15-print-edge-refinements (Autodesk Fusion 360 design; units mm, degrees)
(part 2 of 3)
sketch "B Facet 180 Triangle 3" plane through (0, -75, 0) normal (0, -1, 0) x axis (-1, 0, 0)
  line L1 (60.9665, 27.066) -> (-2.067, -27.066)
  line L2 (124, -27.066) -> (60.9665, 27.066)
  line L3 (-2.067, -27.066) -> (124, -27.066)
  line L4 (60.9665, 21.7934) -> (8.7304, -23.066)
  line L5 (113.2026, -23.066) -> (60.9665, 21.7934)
  line L6 (8.7304, -23.066) -> (113.2026, -23.066)
  point P1 (0, 0)
  point P2 (-2.067, -27.066)
  point P3 (60.9665, 27.066)
  point P4 (124, -27.066)
  dimension "d477" distance P1 P2 = 2.067 (= "Linear Dimension-2")
  dimension "d478" distance P1 P2 = 27.066 (= "Linear Dimension-3")
  dimension "d479" distance P1 P3 = 60.9665 (= "Linear Dimension-4")
  dimension "d480" distance P1 P3 = 27.066 (= "Linear Dimension-5")
  dimension "d481" distance P1 P4 = 124 (= "Linear Dimension-6")
  dimension "d482" distance P1 P4 = 27.066 (= "Linear Dimension-7")
  dimension "d483" = 4 (= "memberWidth / 2")
extrude "Extrude14" cut sketch "B Facet 180 Triangle 3" profile of L5 L6 L4 against normal blind 4.7 (magnitude of "-( wall + 0.2 mm )")
sketch "B Facet 180 Triangle 4" plane through (0, -75, 0) normal (0, -1, 0) x axis (-1, 0, 0)
  line L1 (124, -27.066) -> (60.9665, 27.066)
  line L2 (124, 27.066) -> (124, -27.066)
  line L3 (60.9665, 27.066) -> (124, 27.066)
  line L4 (120, -18.3583) -> (71.7639, 23.066)
  line L5 (120, 23.066) -> (120, -18.3583)
  line L6 (71.7639, 23.066) -> (120, 23.066)
  point P1 (0, 0)
  point P2 (60.9665, 27.066)
  point P3 (124, -27.066)
  point P4 (124, 27.066)
  dimension "d486" distance P1 P2 = 60.9665 (= "Linear Dimension-2")
  dimension "d487" distance P1 P2 = 27.066 (= "Linear Dimension-3")
  dimension "d488" distance P1 P3 = 124 (= "Linear Dimension-4")
  dimension "d489" distance P1 P3 = 27.066 (= "Linear Dimension-5")
  dimension "d490" distance P1 P4 = 124 (= "Linear Dimension-6")
  dimension "d491" distance P1 P4 = 27.066 (= "Linear Dimension-7")
  dimension "d492" = -4 (= "-memberWidth / 2")
extrude "Extrude15" cut sketch "B Facet 180 Triangle 4" profile of L5 L6 L4 against normal blind 4.7 (magnitude of "-( wall + 0.2 mm )")
fillet "Fillet5" radius 1.5 (= "apertureRadius")
work_plane "WorkPlane11" RotateAngle 135 ExtraOffset 0
work_plane "WorkPlane12" AlongDistance 75 (= "bodyWidth / 2") ExtraOffset 0
sketch "B Facet 225 Triangle 1" plane through (0, -53.033, -53.033) normal (0, -0.7071, -0.7071) x axis (1, 0, 0)
  line L1 (23.9949, -27.066) -> (62.2721, 27.066)
  line L2 (0.1814, 27.066) -> (23.9949, -27.066)
  line L3 (62.2721, 27.066) -> (0.1814, 27.066)
  line L4 (24.81, -18.9852) -> (54.5447, 23.066)
  line L5 (6.311, 23.066) -> (24.81, -18.9852)
  line L6 (54.5447, 23.066) -> (6.311, 23.066)
  point P1 (0, 0)
  point P2 (62.2721, 27.066)
  point P3 (23.9949, -27.066)
  point P4 (0.1814, 27.066)
  dimension "d501" distance P1 P2 = 62.2721 (= "Linear Dimension-2")
  dimension "d502" distance P1 P2 = 27.066 (= "Linear Dimension-3")
  dimension "d503" distance P1 P3 = 23.9949 (= "Linear Dimension-4")
  dimension "d504" distance P1 P3 = 27.066 (= "Linear Dimension-5")
  dimension "d505" distance P1 P4 = 0.1814 (= "Linear Dimension-6")
  dimension "d506" distance P1 P4 = 27.066 (= "Linear Dimension-7")
  dimension "d507" = 4 (= "memberWidth / 2")
extrude "Extrude16" cut sketch "B Facet 225 Triangle 1" profile of L5 L6 L4 against normal blind 4.7 (magnitude of "-( wall + 0.2 mm )")
sketch "B Facet 225 Triangle 2" plane through (0, -53.033, -53.033) normal (0, -0.7071, -0.7071) x axis (1, 0, 0)
  line L1 (0.1814, 27.066) -> (23.9949, -27.066)
  line L2 (-74.6684, -27.066) -> (0.1814, 27.066)
  line L3 (23.9949, -27.066) -> (-74.6684, -27.066)
  line L4 (-1.4863, 20.9235) -> (17.8653, -23.066)
  line L5 (-62.3117, -23.066) -> (-1.4863, 20.9235)
  line L6 (17.8653, -23.066) -> (-62.3117, -23.066)
  point P1 (0, 0)
  point P2 (23.9949, -27.066)
  point P3 (0.1814, 27.066)
  point P4 (-74.6684, -27.066)
  dimension "d510" distance P1 P2 = 23.9949 (= "Linear Dimension-2")
  dimension "d511" distance P1 P2 = 27.066 (= "Linear Dimension-3")
  dimension "d512" distance P1 P3 = 0.1814 (= "Linear Dimension-4")
  dimension "d513" distance P1 P3 = 27.066 (= "Linear Dimension-5")
  dimension "d514" distance P1 P4 = 74.6684 (= "Linear Dimension-6")
  dimension "d515" distance P1 P4 = 27.066 (= "Linear Dimension-7")
  dimension "d516" = -4 (= "-memberWidth / 2")
extrude "Extrude17" cut sketch "B Facet 225 Triangle 2" profile of L5 L6 L4 against normal blind 4.7 (magnitude of "-( wall + 0.2 mm )")
sketch "B Facet 225 Triangle 3" plane through (0, -53.033, -53.033) normal (0, -0.7071, -0.7071) x axis (1, 0, 0)
  line L1 (-74.6684, -27.066) -> (0.1814, 27.066)
  line L2 (-124, 27.066) -> (-74.6684, -27.066)
  line L3 (0.1814, 27.066) -> (-124, 27.066)
  line L4 (-74.1179, -21.7315) -> (-12.1753, 23.066)
  line L5 (-114.9429, 23.066) -> (-74.1179, -21.7315)
  line L6 (-12.1753, 23.066) -> (-114.9429, 23.066)
  point P1 (0, 0)
  point P2 (0.1814, 27.066)
  point P3 (-74.6684, -27.066)
  point P4 (-124, 27.066)
  dimension "d519" distance P1 P2 = 0.1814 (= "Linear Dimension-2")
  dimension "d520" distance P1 P2 = 27.066 (= "Linear Dimension-3")
  dimension "d521" distance P1 P3 = 74.6684 (= "Linear Dimension-4")
  dimension "d522" distance P1 P3 = 27.066 (= "Linear Dimension-5")
  dimension "d523" distance P1 P4 = 124 (= "Linear Dimension-6")
  dimension "d524" distance P1 P4 = 27.066 (= "Linear Dimension-7")
  dimension "d525" = 4 (= "memberWidth / 2")
extrude "Extrude18" cut sketch "B Facet 225 Triangle 3" profile of L5 L6 L4 against normal blind 4.7 (magnitude of "-( wall + 0.2 mm )")
sketch "B Facet 225 Triangle 4" plane through (0, -53.033, -53.033) normal (0, -0.7071, -0.7071) x axis (1, 0, 0)
  line L1 (-124, 27.066) -> (-74.6684, -27.066)
  line L2 (-124, -27.066) -> (-124, 27.066)
  line L3 (-74.6684, -27.066) -> (-124, -27.066)
  line L4 (-120, 16.7383) -> (-83.7255, -23.066)
  line L5 (-120, -23.066) -> (-120, 16.7383)
  line L6 (-83.7255, -23.066) -> (-120, -23.066)
  point P1 (0, 0)
  point P2 (-74.6684, -27.066)
  point P3 (-124, 27.066)
  point P4 (-124, -27.066)
  dimension "d528" distance P1 P2 = 74.6684 (= "Linear Dimension-2")
  dimension "d529" distance P1 P2 = 27.066 (= "Linear Dimension-3")
  dimension "d530" distance P1 P3 = 124 (= "Linear Dimension-4")
  dimension "d531" distance P1 P3 = 27.066 (= "Linear Dimension-5")
  dimension "d532" distance P1 P4 = 124 (= "Linear Dimension-6")
  dimension "d533" distance P1 P4 = 27.066 (= "Linear Dimension-7")
  dimension "d534" = -4 (= "-memberWidth / 2")
extrude "Extrude19" cut sketch "B Facet 225 Triangle 4" profile of L5 L6 L4 against normal blind 4.7 (magnitude of "-( wall + 0.2 mm )")
fillet "Fillet6" radius 1.5 (= "apertureRadius")
work_plane "WorkPlane13" RotateAngle 180 ExtraOffset 0
work_plane "WorkPlane14" AlongDistance 75 (= "bodyWidth / 2") ExtraOffset 0
sketch "B Facet 270 Triangle 1" plane through (0, 0, -75) normal (0, 0, -1) x axis (-1, 0, 0)
  line L1 (36.9655, 27.066) -> (-17.1665, -27.066)
  line L2 (53.4167, -27.066) -> (36.9655, 27.066)
  line L3 (-17.1665, -27.066) -> (53.4167, -27.066)
  line L4 (35.0777, 19.5214) -> (-7.5097, -23.066)
  line L5 (48.0205, -23.066) -> (35.0777, 19.5214)
  line L6 (-7.5097, -23.066) -> (48.0205, -23.066)
  point P1 (0, 0)
  point P2 (-17.1665, -27.066)
  point P3 (36.9655, 27.066)
  point P4 (53.4167, -27.066)
  dimension "d543" distance P1 P2 = 17.1665 (= "Linear Dimension-2")
  dimension "d544" distance P1 P2 = 27.066 (= "Linear Dimension-3")
  dimension "d545" distance P1 P3 = 36.9655 (= "Linear Dimension-4")
  dimension "d546" distance P1 P3 = 27.066 (= "Linear Dimension-5")
  dimension "d547" distance P1 P4 = 53.4167 (= "Linear Dimension-6")
  dimension "d548" distance P1 P4 = 27.066 (= "Linear Dimension-7")
  dimension "d549" = 4 (= "memberWidth / 2")
extrude "Extrude20" cut sketch "B Facet 270 Triangle 1" profile of L5 L6 L4 against normal blind 4.7 (magnitude of "-( wall + 0.2 mm )")
sketch "B Facet 270 Triangle 2" plane through (0, 0, -75) normal (0, 0, -1) x axis (-1, 0, 0)
  line L1 (53.4167, -27.066) -> (36.9655, 27.066)
  line L2 (124, 27.066) -> (53.4167, -27.066)
  line L3 (36.9655, 27.066) -> (124, 27.066)
  line L4 (55.5648, -20.3777) -> (42.3618, 23.066)
  line L5 (112.2115, 23.066) -> (55.5648, -20.3777)
  line L6 (42.3618, 23.066) -> (112.2115, 23.066)
  point P1 (0, 0)
  point P2 (36.9655, 27.066)
  point P3 (53.4167, -27.066)
  point P4 (124, 27.066)
  dimension "d552" distance P1 P2 = 36.9655 (= "Linear Dimension-2")
  dimension "d553" distance P1 P2 = 27.066 (= "Linear Dimension-3")
  dimension "d554" distance P1 P3 = 53.4167 (= "Linear Dimension-4")
  dimension "d555" distance P1 P3 = 27.066 (= "Linear Dimension-5")
  dimension "d556" distance P1 P4 = 124 (= "Linear Dimension-6")
  dimension "d557" distance P1 P4 = 27.066 (= "Linear Dimension-7")
  dimension "d558" = -4 (= "-memberWidth / 2")
extrude "Extrude21" cut sketch "B Facet 270 Triangle 2" profile of L5 L6 L4 against normal blind 4.7 (magnitude of "-( wall + 0.2 mm )")
sketch "B Facet 270 Triangle 3" plane through (0, 0, -75) normal (0, 0, -1) x axis (-1, 0, 0)
  line L1 (124, 27.066) -> (53.4167, -27.066)
  line L2 (124, -27.066) -> (124, 27.066)
  line L3 (53.4167, -27.066) -> (124, -27.066)
  line L4 (120, 18.9574) -> (65.2053, -23.066)
  line L5 (120, -23.066) -> (120, 18.9574)
  line L6 (65.2053, -23.066) -> (120, -23.066)
  point P1 (0, 0)
  point P2 (53.4167, -27.066)
  point P3 (124, 27.066)
  point P4 (124, -27.066)
  dimension "d561" distance P1 P2 = 53.4167 (= "Linear Dimension-2")
  dimension "d562" distance P1 P2 = 27.066 (= "Linear Dimension-3")
  dimension "d563" distance P1 P3 = 124 (= "Linear Dimension-4")
  dimension "d564" distance P1 P3 = 27.066 (= "Linear Dimension-5")
  dimension "d565" distance P1 P4 = 124 (= "Linear Dimension-6")
  dimension "d566" distance P1 P4 = 27.066 (= "Linear Dimension-7")
  dimension "d567" = 4 (= "memberWidth / 2")
extrude "Extrude22" cut sketch "B Facet 270 Triangle 3" profile of L5 L6 L4 against normal blind 4.7 (magnitude of "-( wall + 0.2 mm )")
fillet "Fillet7" radius 1.5 (= "apertureRadius")
work_plane "WorkPlane15" RotateAngle 225 ExtraOffset 0
work_plane "WorkPlane16" AlongDistance 75 (= "bodyWidth / 2") ExtraOffset 0
sketch "B Facet 315 Triangle 1" plane through (0, 53.033, -53.033) normal (0, 0.7071, -0.7071) x axis (1, 0, 0)
  line L1 (-82.0711, -27.066) -> (-43.7939, 27.066)
  line L2 (-124, 27.066) -> (-82.0711, -27.066)
  line L3 (-43.7939, 27.066) -> (-124, 27.066)
  line L4 (-82.2175, -20.3449) -> (-51.5213, 23.066)
  line L5 (-115.8422, 23.066) -> (-82.2175, -20.3449)
  line L6 (-51.5213, 23.066) -> (-115.8422, 23.066)
  point P1 (0, 0)
  point P2 (-43.7939, 27.066)
  point P3 (-82.0711, -27.066)
  point P4 (-124, 27.066)
  dimension "d576" distance P1 P2 = 43.7939 (= "Linear Dimension-2")
  dimension "d577" distance P1 P2 = 27.066 (= "Linear Dimension-3")
  dimension "d578" distance P1 P3 = 82.0711 (= "Linear Dimension-4")
  dimension "d579" distance P1 P3 = 27.066 (= "Linear Dimension-5")
  dimension "d580" distance P1 P4 = 124 (= "Linear Dimension-6")
  dimension "d581" distance P1 P4 = 27.066 (= "Linear Dimension-7")
  dimension "d582" = 4 (= "memberWidth / 2")
extrude "Extrude23" cut sketch "B Facet 315 Triangle 1" profile of L5 L6 L4 against normal blind 4.7 (magnitude of "-( wall + 0.2 mm )")
sketch "B Facet 315 Triangle 2" plane through (0, 53.033, -53.033) normal (0, 0.7071, -0.7071) x axis (1, 0, 0)
  line L1 (-124, 27.066) -> (-82.0711, -27.066)
  line L2 (-124, -27.066) -> (-124, 27.066)
  line L3 (-82.0711, -27.066) -> (-124, -27.066)
  line L4 (-120, 15.3697) -> (-90.2289, -23.066)
  line L5 (-120, -23.066) -> (-120, 15.3697)
  line L6 (-90.2289, -23.066) -> (-120, -23.066)
  point P1 (0, 0)
  point P2 (-82.0711, -27.066)
  point P3 (-124, 27.066)
  point P4 (-124, -27.066)
  dimension "d585" distance P1 P2 = 82.0711 (= "Linear Dimension-2")
  dimension "d586" distance P1 P2 = 27.066 (= "Linear Dimension-3")
  dimension "d587" distance P1 P3 = 124 (= "Linear Dimension-4")
  dimension "d588" distance P1 P3 = 27.066 (= "Linear Dimension-5")
  dimension "d589" distance P1 P4 = 124 (= "Linear Dimension-6")
  dimension "d590" distance P1 P4 = 27.066 (= "Linear Dimension-7")
  dimension "d591" = -4 (= "-memberWidth / 2")
extrude "Extrude24" cut sketch "B Facet 315 Triangle 2" profile of L5 L6 L4 against normal blind 4.7 (magnitude of "-( wall + 0.2 mm )")
fillet "Fillet8" radius 1.5 (= "apertureRadius")
work_plane "WorkPlane17" AlongDistance 0.5 (= "qFront") ExtraOffset 0
sketch "A Central Carrier sketch" plane through (0.3536, 0.3536, 0) normal (0.7071, 0.7071, 0) x axis (0, 0, 1)
  circle C1 centre (0, 0) radius 26
  dimension "d598" diameter C1 = 52 (= "carrierOD")
extrude "Extrude25" new body sketch "A Central Carrier sketch" along normal blind 18 (= "spokeDepth")
work_plane "WorkPlane18" AlongDistance 0.5 (= "qFront") ExtraOffset 0
sketch "A Spoke 1 Profile" plane through (0.3536, 0.3536, 0) normal (0.7071, 0.7071, 0) x axis (0, 0, 1)
  line L1 (37.3643, -145.3579) -> (-4.7984, -1.4054)
  line L2 (46.9611, -142.547) -> (37.3643, -145.3579)
  line L3 (4.7984, 1.4054) -> (46.9611, -142.547)
  line L4 (-4.7984, -1.4054) -> (4.7984, 1.4054)
  point P1 (0, 0)
  point P2 (-4.7984, -1.4054)
  point P3 (37.3643, -145.3579)
  point P4 (46.9611, -142.547)
  point P5 (4.7984, 1.4054)
  dimension "d603" distance P1 P2 = 4.7984 (= "Linear Dimension-2")
  dimension "d604" distance P1 P2 = 1.4054 (= "Linear Dimension-3")
  dimension "d605" distance P1 P3 = 37.3643 (= "Linear Dimension-4")
  dimension "d606" distance P1 P3 = 145.3579 (= "Linear Dimension-5")
  dimension "d607" distance P1 P4 = 46.9611 (= "Linear Dimension-6")
  dimension "d608" distance P1 P4 = 142.547 (= "Linear Dimension-7")
  dimension "d609" distance P1 P5 = 4.7984 (= "Linear Dimension-8")
  dimension "d610" distance P1 P5 = 1.4054 (= "Linear Dimension-9")
extrude "Extrude26" add sketch "A Spoke 1 Profile" along normal blind 18 (= "spokeDepth")
sketch "A Spoke 2 Profile" plane through (0.3536, 0.3536, 0) normal (0.7071, 0.7071, 0) x axis (0, 0, 1)
  line L1 (126.9012, -80.1317) -> (-2.5272, -4.3143)
  line L2 (131.9557, -71.5031) -> (126.9012, -80.1317)
  line L3 (2.5272, 4.3143) -> (131.9557, -71.5031)
  line L4 (-2.5272, -4.3143) -> (2.5272, 4.3143)
  point P1 (0, 0)
  point P2 (-2.5272, -4.3143)
  point P3 (126.9012, -80.1317)
  point P4 (131.9557, -71.5031)
  point P5 (2.5272, 4.3143)
  dimension "d613" distance P1 P2 = 2.5272 (= "Linear Dimension-2")
  dimension "d614" distance P1 P2 = 4.3143 (= "Linear Dimension-3")
  dimension "d615" distance P1 P3 = 126.9012 (= "Linear Dimension-4")
  dimension "d616" distance P1 P3 = 80.1317 (= "Linear Dimension-5")
  dimension "d617" distance P1 P4 = 131.9557 (= "Linear Dimension-6")
  dimension "d618" distance P1 P4 = 71.5031 (= "Linear Dimension-7")
  dimension "d619" distance P1 P5 = 2.5272 (= "Linear Dimension-8")
  dimension "d620" distance P1 P5 = 4.3143 (= "Linear Dimension-9")
extrude "Extrude27" add sketch "A Spoke 2 Profile" along normal blind 18 (= "spokeDepth")
sketch "A Spoke 3 Profile" plane through (0.3536, 0.3536, 0) normal (0.7071, 0.7071, 0) x axis (0, 0, 1)
  line L1 (131.9557, 71.5031) -> (2.5272, -4.3143)
  line L2 (126.9012, 80.1317) -> (131.9557, 71.5031)
  line L3 (-2.5272, 4.3143) -> (126.9012, 80.1317)
  line L4 (2.5272, -4.3143) -> (-2.5272, 4.3143)
  point P1 (0, 0)
  point P2 (2.5272, -4.3143)
  point P3 (131.9557, 71.5031)
  point P4 (126.9012, 80.1317)
  point P5 (-2.5272, 4.3143)
  dimension "d623" distance P1 P2 = 2.5272 (= "Linear Dimension-2")
  dimension "d624" distance P1 P2 = 4.3143 (= "Linear Dimension-3")
  dimension "d625" distance P1 P3 = 131.9557 (= "Linear Dimension-4")
  dimension "d626" distance P1 P3 = 71.5031 (= "Linear Dimension-5")
  dimension "d627" distance P1 P4 = 126.9012 (= "Linear Dimension-6")
  dimension "d628" distance P1 P4 = 80.1317 (= "Linear Dimension-7")
  dimension "d629" distance P1 P5 = 2.5272 (= "Linear Dimension-8")
  dimension "d630" distance P1 P5 = 4.3143 (= "Linear Dimension-9")
extrude "Extrude28" add sketch "A Spoke 3 Profile" along normal blind 18 (= "spokeDepth")
sketch "A Spoke 4 Profile" plane through (0.3536, 0.3536, 0) normal (0.7071, 0.7071, 0) x axis (0, 0, 1)
  line L1 (46.9611, 142.547) -> (4.7984, -1.4054)
  line L2 (37.3643, 145.3579) -> (46.9611, 142.547)
  line L3 (-4.7984, 1.4054) -> (37.3643, 145.3579)
  line L4 (4.7984, -1.4054) -> (-4.7984, 1.4054)
  point P1 (0, 0)
  point P2 (4.7984, -1.4054)
  point P3 (46.9611, 142.547)
  point P4 (37.3643, 145.3579)
  point P5 (-4.7984, 1.4054)
  dimension "d633" distance P1 P2 = 4.7984 (= "Linear Dimension-2")
  dimension "d634" distance P1 P2 = 1.4054 (= "Linear Dimension-3")
  dimension "d635" distance P1 P3 = 46.9611 (= "Linear Dimension-4")
  dimension "d636" distance P1 P3 = 142.547 (= "Linear Dimension-5")
  dimension "d637" distance P1 P4 = 37.3643 (= "Linear Dimension-6")
  dimension "d638" distance P1 P4 = 145.3579 (= "Linear Dimension-7")
  dimension "d639" distance P1 P5 = 4.7984 (= "Linear Dimension-8")
  dimension "d640" distance P1 P5 = 1.4054 (= "Linear Dimension-9")
extrude "Extrude29" add sketch "A Spoke 4 Profile" along normal blind 18 (= "spokeDepth")
sketch "A Spoke 5 Profile" plane through (0.3536, 0.3536, 0) normal (0.7071, 0.7071, 0) x axis (0, 0, 1)
  line L1 (-37.3643, 145.3579) -> (4.7984, 1.4054)
  line L2 (-46.9611, 142.547) -> (-37.3643, 145.3579)
  line L3 (-4.7984, -1.4054) -> (-46.9611, 142.547)
  line L4 (4.7984, 1.4054) -> (-4.7984, -1.4054)
  point P1 (0, 0)
  point P2 (4.7984, 1.4054)
  point P3 (-37.3643, 145.3579)
  point P4 (-46.9611, 142.547)
  point P5 (-4.7984, -1.4054)
  dimension "d643" distance P1 P2 = 4.7984 (= "Linear Dimension-2")
  dimension "d644" distance P1 P2 = 1.4054 (= "Linear Dimension-3")
  dimension "d645" distance P1 P3 = 37.3643 (= "Linear Dimension-4")
  dimension "d646" distance P1 P3 = 145.3579 (= "Linear Dimension-5")
  dimension "d647" distance P1 P4 = 46.9611 (= "Linear Dimension-6")
  dimension "d648" distance P1 P4 = 142.547 (= "Linear Dimension-7")
  dimension "d649" distance P1 P5 = 4.7984 (= "Linear Dimension-8")
  dimension "d650" distance P1 P5 = 1.4054 (= "Linear Dimension-9")
extrude "Extrude30" add sketch "A Spoke 5 Profile" along normal blind 18 (= "spokeDepth")
sketch "A Spoke 6 Profile" plane through (0.3536, 0.3536, 0) normal (0.7071, 0.7071, 0) x axis (0, 0, 1)
  line L1 (-126.9012, 80.1317) -> (2.5272, 4.3143)
  line L2 (-131.9557, 71.5031) -> (-126.9012, 80.1317)
  line L3 (-2.5272, -4.3143) -> (-131.9557, 71.5031)
  line L4 (2.5272, 4.3143) -> (-2.5272, -4.3143)
  point P1 (0, 0)
  point P2 (2.5272, 4.3143)
  point P3 (-126.9012, 80.1317)
  point P4 (-131.9557, 71.5031)
  point P5 (-2.5272, -4.3143)
  dimension "d653" distance P1 P2 = 2.5272 (= "Linear Dimension-2")
  dimension "d654" distance P1 P2 = 4.3143 (= "Linear Dimension-3")
  dimension "d655" distance P1 P3 = 126.9012 (= "Linear Dimension-4")
  dimension "d656" distance P1 P3 = 80.1317 (= "Linear Dimension-5")
  dimension "d657" distance P1 P4 = 131.9557 (= "Linear Dimension-6")
  dimension "d658" distance P1 P4 = 71.5031 (= "Linear Dimension-7")
  dimension "d659" distance P1 P5 = 2.5272 (= "Linear Dimension-8")
  dimension "d660" distance P1 P5 = 4.3143 (= "Linear Dimension-9")
extrude "Extrude31" add sketch "A Spoke 6 Profile" along normal blind 18 (= "spokeDepth")
sketch "A Spoke 7 Profile" plane through (0.3536, 0.3536, 0) normal (0.7071, 0.7071, 0) x axis (0, 0, 1)
  line L1 (-131.9557, -71.5031) -> (-2.5272, 4.3143)
  line L2 (-126.9012, -80.1317) -> (-131.9557, -71.5031)
  line L3 (2.5272, -4.3143) -> (-126.9012, -80.1317)
  line L4 (-2.5272, 4.3143) -> (2.5272, -4.3143)
  point P1 (0, 0)
  point P2 (-2.5272, 4.3143)
  point P3 (-131.9557, -71.5031)
  point P4 (-126.9012, -80.1317)
  point P5 (2.5272, -4.3143)
  dimension "d663" distance P1 P2 = 2.5272 (= "Linear Dimension-2")
  dimension "d664" distance P1 P2 = 4.3143 (= "Linear Dimension-3")
  dimension "d665" distance P1 P3 = 131.9557 (= "Linear Dimension-4")
  dimension "d666" distance P1 P3 = 71.5031 (= "Linear Dimension-5")
  dimension "d667" distance P1 P4 = 126.9012 (= "Linear Dimension-6")
  dimension "d668" distance P1 P4 = 80.1317 (= "Linear Dimension-7")
  dimension "d669" distance P1 P5 = 2.5272 (= "Linear Dimension-8")
  dimension "d670" distance P1 P5 = 4.3143 (= "Linear Dimension-9")
extrude "Extrude32" add sketch "A Spoke 7 Profile" along normal blind 18 (= "spokeDepth")
sketch "A Spoke 8 Profile" plane through (0.3536, 0.3536, 0) normal (0.7071, 0.7071, 0) x axis (0, 0, 1)
  line L1 (-46.9611, -142.547) -> (-4.7984, 1.4054)
  line L2 (-37.3643, -145.3579) -> (-46.9611, -142.547)
  line L3 (4.7984, 1.4054) -> (-37.3643, -145.3579)
  line L4 (-4.7984, 1.4054) -> (4.7984, 1.4054)
  point P1 (0, 0)
  point P2 (-4.7984, 1.4054)
  point P3 (-46.9611, -142.547)
  point P4 (-37.3643, -145.3579)
  point P5 (4.7984, 1.4054)
  dimension "d673" distance P1 P2 = 4.7984 (= "Linear Dimension-2")
  dimension "d674" distance P1 P2 = 1.4054 (= "Linear Dimension-3")
  dimension "d675" distance P1 P3 = 46.9611 (= "Linear Dimension-4")
  dimension "d676" distance P1 P3 = 142.547 (= "Linear Dimension-5")
  dimension "d677" distance P1 P4 = 37.3643 (= "Linear Dimension-6")
  dimension "d678" distance P1 P4 = 145.3579 (= "Linear Dimension-7")
  dimension "d679" distance P1 P5 = 4.7984 (= "Linear Dimension-8")
  dimension "d680" distance P1 P5 = 1.4054 (= "Linear Dimension-9")
extrude "Extrude33" add sketch "A Spoke 8 Profile" along normal blind 18 (= "spokeDepth")
sketch "Spoke Outer Envelope" plane through (0, 0, 0) normal (1, 0, 0) x axis (0, 0, -1)
  line L1 (31.066, 75) -> (75, 31.066)
  line L2 (-31.066, 75) -> (31.066, 75)
  line L3 (-75, 31.066) -> (-31.066, 75)
  line L4 (-75, -31.066) -> (-75, 31.066)
  line L5 (-31.066, -75) -> (-75, -31.066)
  line L6 (31.066, -75) -> (-31.066, -75)
  line L7 (75, -31.066) -> (31.066, -75)
  line L8 (75, 31.066) -> (75, -31.066)
  point P1 (0, 0)
  point P10 (0, 0)
  point P3 (31.066, 75)
  point P8 (31.066, -75)
  coincident P1 P10
  horizontal L2
  dimension "d683" distance P3 P8 = 150 (= "bodyWidth")
extrude "Extrude34" sketch "Spoke Outer Envelope" distance 260 (= "bodyLength")
fillet "Fillet9" radius 1 (= "rootRadius")
work_plane "WorkPlane19" AlongDistance 10.6 (= "qFrontBack") ExtraOffset 0
sketch "A Rear Carrier Clearance sketch" plane through (7.4953, 7.4953, 0) normal (0.7071, 0.7071, 0) x axis (0, 0, 1)
  circle C1 centre (0, 0) radius 23
  dimension "d690" diameter C1 = 46 (= "rearCarrierClearance")
extrude "Extrude35" cut sketch "A Rear Carrier Clearance sketch" along normal blind 18 (= "spokeDepth")
work_plane "WorkPlane20" AlongDistance 0.5 (= "qFront") ExtraOffset 0
sketch "A Seal Relief sketch" plane through (0.3536, 0.3536, 0) normal (0.7071, 0.7071, 0) x axis (0, 0, 1)
  circle C1 centre (0, 0) radius 9.75
  dimension "d695" diameter C1 = 19.5 (= "raceRelief")
extrude "Extrude36" cut sketch "A Seal Relief sketch" along normal blind 10.1 (= "frontSeatDepth + shoulder")
work_plane "WorkPlane21" AlongDistance 0.5 (= "qFront") ExtraOffset 0
sketch "A Front Bearing Seat sketch" plane through (0.3536, 0.3536, 0) normal (0.7071, 0.7071, 0) x axis (0, 0, 1)
  circle C1 centre (0, 0) radius 11.1
  dimension "d700" diameter C1 = 22.2 (= "seatDiameter")
extrude "Extrude37" cut sketch "A Front Bearing Seat sketch" along normal blind 7.1 (= "frontSeatDepth")
work_plane "WorkPlane22" AlongDistance 0.5 (= "qFront") ExtraOffset 0
sketch "A Support Bolt seed" plane through (0.3536, 0.3536, 0) normal (0.7071, 0.7071, 0) x axis (0, 0, 1)
  line L1 (17, 0) -> (0, 0)
  circle C1 centre (17, 0) radius 1.65
  point P1 (0, 0)
  point P2 (17, 0)
  horizontal L1
  dimension "d705" distance P1 P2 = 17 (= "supportCircle / 2")
  dimension "d706" diameter C1 = 3.3 (= "m3Clearance")
extrude "Extrude38" cut sketch "A Support Bolt seed" profile of C1 along normal blind 10.1 (= "frontSeatDepth + shoulder")
circular_pattern "C-Pattern1" TotalAngle 360
work_plane "WorkPlane23" AlongDistance 0.5 (= "qFront") ExtraOffset 0
sketch "A Front Bearing Boss sketch" plane through (0.3536, 0.3536, 0) normal (0.7071, 0.7071, 0) x axis (0, 0, 1)
  circle C1 centre (0, 0) radius 22
  dimension "d713" diameter C1 = 44 (= "coreOD")
chamfer "Chamfer1" distance 0.4 (= "entryChamfer")
work_plane "WorkPlane24" AlongDistance 75 (= "bodyWidth / 2") ExtraOffset 0
sketch "A Collar Driver Corridors" plane through (0, 0, 75) normal (0, 0, 1) x axis (1, 0, 0)
  circle C1 centre (6.7175, 15.9099) radius 3
  circle C2 centre (15.9099, 6.7175) radius 3
  point P1 (0, 0)
  point P2 (6.7175, 15.9099)
  point P3 (15.9099, 6.7175)
  dimension "d717" distance P1 P2 = 6.7175 (= "abs(( 16 mm + ( -6.5 mm ) ) / sqrt(2))")
  dimension "d718" distance P1 P2 = 15.9099 (= "abs(( 16 mm - ( -6.5 mm ) ) / sqrt(2))")
  dimension "d719" diameter C1 = 6
  dimension "d720" distance P1 P3 = 15.9099 (= "abs(( 16 mm + ( 6.5 mm ) ) / sqrt(2))")
  dimension "d721" distance P1 P3 = 6.7175 (= "abs(( 16 mm - ( 6.5 mm ) ) / sqrt(2))")
  dimension "d722" diameter C2 = 6
extrude "Extrude39" cut sketch "A Collar Driver Corridors" against normal blind 75 (magnitude of "-( bodyWidth / 2 )")
work_plane "WorkPlane17" ExtraOffset 0
sketch "B Central Carrier sketch" plane through (-0.3536, -0.3536, 0) normal (0.7071, 0.7071, 0) x axis (0, 0, 1)
  circle C1 centre (0, 0) radius 38
  dimension "d727" diameter C1 = 76 (= "mountOD")
extrude "Extrude25" new body sketch "B Central Carrier sketch" no distance stored
work_plane "WorkPlane18" ExtraOffset 0
sketch "B Spoke 1 Profile" plane through (-0.3536, -0.3536, 0) normal (0.7071, 0.7071, 0) x axis (0, 0, 1)
  line L1 (37.3643, -145.3579) -> (-4.7984, -1.4054)
  line L2 (46.9611, -142.547) -> (37.3643, -145.3579)
  line L3 (4.7984, 1.4054) -> (46.9611, -142.547)
  line L4 (-4.7984, -1.4054) -> (4.7984, 1.4054)
  point P1 (0, 0)
  point P2 (-4.7984, -1.4054)
  point P3 (37.3643, -145.3579)
  point P4 (46.9611, -142.547)
  point P5 (4.7984, 1.4054)
  dimension "d732" distance P1 P2 = 4.7984 (= "Linear Dimension-2")
  dimension "d733" distance P1 P2 = 1.4054 (= "Linear Dimension-3")
  dimension "d734" distance P1 P3 = 37.3643 (= "Linear Dimension-4")
  dimension "d735" distance P1 P3 = 145.3579 (= "Linear Dimension-5")
  dimension "d736" distance P1 P4 = 46.9611 (= "Linear Dimension-6")
  dimension "d737" distance P1 P4 = 142.547 (= "Linear Dimension-7")
  dimension "d738" distance P1 P5 = 4.7984 (= "Linear Dimension-8")
  dimension "d739" distance P1 P5 = 1.4054 (= "Linear Dimension-9")
extrude "Extrude26" add sketch "B Spoke 1 Profile" no distance stored
sketch "B Spoke 2 Profile" plane through (-0.3536, -0.3536, 0) normal (0.7071, 0.7071, 0) x axis (0, 0, 1)
  line L1 (126.9012, -80.1317) -> (-2.5272, -4.3143)
  line L2 (131.9557, -71.5031) -> (126.9012, -80.1317)
  line L3 (2.5272, 4.3143) -> (131.9557, -71.5031)
  line L4 (-2.5272, -4.3143) -> (2.5272, 4.3143)
  point P1 (0, 0)
  point P2 (-2.5272, -4.3143)
  point P3 (126.9012, -80.1317)
  point P4 (131.9557, -71.5031)
  point P5 (2.5272, 4.3143)
  dimension "d742" distance P1 P2 = 2.5272 (= "Linear Dimension-2")
  dimension "d743" distance P1 P2 = 4.3143 (= "Linear Dimension-3")
  dimension "d744" distance P1 P3 = 126.9012 (= "Linear Dimension-4")
  dimension "d745" distance P1 P3 = 80.1317 (= "Linear Dimension-5")
  dimension "d746" distance P1 P4 = 131.9557 (= "Linear Dimension-6")
  dimension "d747" distance P1 P4 = 71.5031 (= "Linear Dimension-7")
  dimension "d748" distance P1 P5 = 2.5272 (= "Linear Dimension-8")
  dimension "d749" distance P1 P5 = 4.3143 (= "Linear Dimension-9")
extrude "Extrude27" add sketch "B Spoke 2 Profile" no distance stored
sketch "B Spoke 3 Profile" plane through (-0.3536, -0.3536, 0) normal (0.7071, 0.7071, 0) x axis (0, 0, 1)
  line L1 (131.9557, 71.5031) -> (2.5272, -4.3143)
  line L2 (126.9012, 80.1317) -> (131.9557, 71.5031)
  line L3 (-2.5272, 4.3143) -> (126.9012, 80.1317)
  line L4 (2.5272, -4.3143) -> (-2.5272, 4.3143)
  point P1 (0, 0)
  point P2 (2.5272, -4.3143)
  point P3 (131.9557, 71.5031)
  point P4 (126.9012, 80.1317)
  point P5 (-2.5272, 4.3143)
  dimension "d752" distance P1 P2 = 2.5272 (= "Linear Dimension-2")
  dimension "d753" distance P1 P2 = 4.3143 (= "Linear Dimension-3")
  dimension "d754" distance P1 P3 = 131.9557 (= "Linear Dimension-4")
  dimension "d755" distance P1 P3 = 71.5031 (= "Linear Dimension-5")
  dimension "d756" distance P1 P4 = 126.9012 (= "Linear Dimension-6")
  dimension "d757" distance P1 P4 = 80.1317 (= "Linear Dimension-7")
  dimension "d758" distance P1 P5 = 2.5272 (= "Linear Dimension-8")
  dimension "d759" distance P1 P5 = 4.3143 (= "Linear Dimension-9")
extrude "Extrude28" add sketch "B Spoke 3 Profile" no distance stored
sketch "B Spoke 4 Profile" plane through (-0.3536, -0.3536, 0) normal (0.7071, 0.7071, 0) x axis (0, 0, 1)
  line L1 (46.9611, 142.547) -> (4.7984, -1.4054)
  line L2 (37.3643, 145.3579) -> (46.9611, 142.547)
  line L3 (-4.7984, 1.4054) -> (37.3643, 145.3579)
  line L4 (4.7984, -1.4054) -> (-4.7984, 1.4054)
  point P1 (0, 0)
  point P2 (4.7984, -1.4054)
  point P3 (46.9611, 142.547)
  point P4 (37.3643, 145.3579)
  point P5 (-4.7984, 1.4054)
  dimension "d762" distance P1 P2 = 4.7984 (= "Linear Dimension-2")
  dimension "d763" distance P1 P2 = 1.4054 (= "Linear Dimension-3")
  dimension "d764" distance P1 P3 = 46.9611 (= "Linear Dimension-4")
  dimension "d765" distance P1 P3 = 142.547 (= "Linear Dimension-5")
  dimension "d766" distance P1 P4 = 37.3643 (= "Linear Dimension-6")
  dimension "d767" distance P1 P4 = 145.3579 (= "Linear Dimension-7")
  dimension "d768" distance P1 P5 = 4.7984 (= "Linear Dimension-8")
  dimension "d769" distance P1 P5 = 1.4054 (= "Linear Dimension-9")
extrude "Extrude29" add sketch "B Spoke 4 Profile" no distance stored
sketch "B Spoke 5 Profile" plane through (-0.3536, -0.3536, 0) normal (0.7071, 0.7071, 0) x axis (0, 0, 1)
  line L1 (-37.3643, 145.3579) -> (4.7984, 1.4054)
  line L2 (-46.9611, 142.547) -> (-37.3643, 145.3579)
  line L3 (-4.7984, -1.4054) -> (-46.9611, 142.547)
  line L4 (4.7984, 1.4054) -> (-4.7984, -1.4054)
  point P1 (0, 0)
  point P2 (4.7984, 1.4054)
  point P3 (-37.3643, 145.3579)
  point P4 (-46.9611, 142.547)
  point P5 (-4.7984, -1.4054)
  dimension "d772" distance P1 P2 = 4.7984 (= "Linear Dimension-2")
  dimension "d773" distance P1 P2 = 1.4054 (= "Linear Dimension-3")
  dimension "d774" distance P1 P3 = 37.3643 (= "Linear Dimension-4")
  dimension "d775" distance P1 P3 = 145.3579 (= "Linear Dimension-5")
  dimension "d776" distance P1 P4 = 46.9611 (= "Linear Dimension-6")
  dimension "d777" distance P1 P4 = 142.547 (= "Linear Dimension-7")
  dimension "d778" distance P1 P5 = 4.7984 (= "Linear Dimension-8")
  dimension "d779" distance P1 P5 = 1.4054 (= "Linear Dimension-9")
extrude "Extrude30" add sketch "B Spoke 5 Profile" no distance stored
sketch "B Spoke 6 Profile" plane through (-0.3536, -0.3536, 0) normal (0.7071, 0.7071, 0) x axis (0, 0, 1)
  line L1 (-126.9012, 80.1317) -> (2.5272, 4.3143)
  line L2 (-131.9557, 71.5031) -> (-126.9012, 80.1317)
  line L3 (-2.5272, -4.3143) -> (-131.9557, 71.5031)
  line L4 (2.5272, 4.3143) -> (-2.5272, -4.3143)
  point P1 (0, 0)
  point P2 (2.5272, 4.3143)
  point P3 (-126.9012, 80.1317)
  point P4 (-131.9557, 71.5031)
  point P5 (-2.5272, -4.3143)
  dimension "d782" distance P1 P2 = 2.5272 (= "Linear Dimension-2")
  dimension "d783" distance P1 P2 = 4.3143 (= "Linear Dimension-3")
  dimension "d784" distance P1 P3 = 126.9012 (= "Linear Dimension-4")
  dimension "d785" distance P1 P3 = 80.1317 (= "Linear Dimension-5")
  dimension "d786" distance P1 P4 = 131.9557 (= "Linear Dimension-6")
  dimension "d787" distance P1 P4 = 71.5031 (= "Linear Dimension-7")
  dimension "d788" distance P1 P5 = 2.5272 (= "Linear Dimension-8")
  dimension "d789" distance P1 P5 = 4.3143 (= "Linear Dimension-9")
extrude "Extrude31" add sketch "B Spoke 6 Profile" no distance stored
sketch "B Spoke 7 Profile" plane through (-0.3536, -0.3536, 0) normal (0.7071, 0.7071, 0) x axis (0, 0, 1)
  line L1 (-131.9557, -71.5031) -> (-2.5272, 4.3143)
  line L2 (-126.9012, -80.1317) -> (-131.9557, -71.5031)
  line L3 (2.5272, -4.3143) -> (-126.9012, -80.1317)
  line L4 (-2.5272, 4.3143) -> (2.5272, -4.3143)
  point P1 (0, 0)
  point P2 (-2.5272, 4.3143)
  point P3 (-131.9557, -71.5031)
  point P4 (-126.9012, -80.1317)
  point P5 (2.5272, -4.3143)
  dimension "d792" distance P1 P2 = 2.5272 (= "Linear Dimension-2")
  dimension "d793" distance P1 P2 = 4.3143 (= "Linear Dimension-3")
  dimension "d794" distance P1 P3 = 131.9557 (= "Linear Dimension-4")
  dimension "d795" distance P1 P3 = 71.5031 (= "Linear Dimension-5")
  dimension "d796" distance P1 P4 = 126.9012 (= "Linear Dimension-6")
  dimension "d797" distance P1 P4 = 80.1317 (= "Linear Dimension-7")
  dimension "d798" distance P1 P5 = 2.5272 (= "Linear Dimension-8")
  dimension "d799" distance P1 P5 = 4.3143 (= "Linear Dimension-9")
extrude "Extrude32" add sketch "B Spoke 7 Profile" no distance stored
sketch "B Spoke 8 Profile" plane through (-0.3536, -0.3536, 0) normal (0.7071, 0.7071, 0) x axis (0, 0, 1)
  line L1 (-46.9611, -142.547) -> (-4.7984, 1.4054)
  line L2 (-37.3643, -145.3579) -> (-46.9611, -142.547)
  line L3 (4.7984, 1.4054) -> (-37.3643, -145.3579)
  line L4 (-4.7984, 1.4054) -> (4.7984, 1.4054)
  point P1 (0, 0)
  point P2 (-4.7984, 1.4054)
  point P3 (-46.9611, -142.547)
  point P4 (-37.3643, -145.3579)
  point P5 (4.7984, 1.4054)
  dimension "d802" distance P1 P2 = 4.7984 (= "Linear Dimension-2")
  dimension "d803" distance P1 P2 = 1.4054 (= "Linear Dimension-3")
  dimension "d804" distance P1 P3 = 46.9611 (= "Linear Dimension-4")
  dimension "d805" distance P1 P3 = 142.547 (= "Linear Dimension-5")
  dimension "d806" distance P1 P4 = 37.3643 (= "Linear Dimension-6")
  dimension "d807" distance P1 P4 = 145.3579 (= "Linear Dimension-7")
  dimension "d808" distance P1 P5 = 4.7984 (= "Linear Dimension-8")
  dimension "d809" distance P1 P5 = 1.4054 (= "Linear Dimension-9")
extrude "Extrude33" add sketch "B Spoke 8 Profile" no distance stored
sketch "Spoke Outer Envelope" plane through (0, 0, 0) normal (1, 0, 0) x axis (0, 0, -1)
  line L1 (31.066, 75) -> (75, 31.066)
  line L2 (-31.066, 75) -> (31.066, 75)
  line L3 (-75, 31.066) -> (-31.066, 75)
  line L4 (-75, -31.066) -> (-75, 31.066)
  line L5 (-31.066, -75) -> (-75, -31.066)
  line L6 (31.066, -75) -> (-31.066, -75)
  line L7 (75, -31.066) -> (31.066, -75)
  line L8 (75, 31.066) -> (75, -31.066)
  point P1 (0, 0)
  point P10 (0, 0)
  point P3 (31.066, 75)
  point P8 (31.066, -75)
  coincident P1 P10
  horizontal L2
  dimension "d812" distance P3 P8 = 150 (= "bodyWidth")
extrude "Extrude34" sketch "Spoke Outer Envelope" distance 260 (= "bodyLength")
fillet "Fillet9" radius 1 (= "rootRadius")
work_plane "WorkPlane19" ExtraOffset 0
sketch "B Open Hub Cavity sketch" plane through (-0.3536, -0.3536, 0) normal (0.7071, 0.7071, 0) x axis (0, 0, 1)
  circle C1 centre (0, 0) radius 25.15
  dimension "d819" diameter C1 = 50.3 (= "mountOpening")
extrude "Extrude35" cut sketch "B Open Hub Cavity sketch" no distance stored
work_plane "WorkPlane20" ExtraOffset 0
sketch "B Four Mount Holes" plane through (-0.3536, -0.3536, 0) normal (0.7071, 0.7071, 0) x axis (0, 0, 1)
  circle C1 centre (22.6274, 22.6274) radius 2.15
  circle C2 centre (-22.6274, 22.6274) radius 2.15
  circle C3 centre (-22.6274, -22.6274) radius 2.15
  circle C4 centre (22.6274, -22.6274) radius 2.15
  point P1 (0, 0)
  point P2 (22.6274, 22.6274)
  point P3 (-22.6274, 22.6274)
  point P4 (-22.6274, -22.6274)
  point P5 (22.6274, -22.6274)
  dimension "d824" distance P1 P2 = 22.6274 (= "abs(mountCircle / ( 2 * sqrt(2) ))")
  dimension "d825" distance P1 P2 = 22.6274 (= "abs(mountCircle / ( 2 * sqrt(2) ))")
  dimension "d826" diameter C1 = 4.3 (= "m4Clearance")
  dimension "d827" distance P1 P3 = 22.6274 (= "abs(-mountCircle / ( 2 * sqrt(2) ))")
  dimension "d828" distance P1 P3 = 22.6274 (= "abs(mountCircle / ( 2 * sqrt(2) ))")
  dimension "d829" diameter C2 = 4.3 (= "m4Clearance")
  dimension "d830" distance P1 P4 = 22.6274 (= "abs(-mountCircle / ( 2 * sqrt(2) ))")
  dimension "d831" distance P1 P4 = 22.6274 (= "abs(-mountCircle / ( 2 * sqrt(2) ))")
  dimension "d832" diameter C3 = 4.3 (= "m4Clearance")
  dimension "d833" distance P1 P5 = 22.6274 (= "abs(mountCircle / ( 2 * sqrt(2) ))")
  dimension "d834" distance P1 P5 = 22.6274 (= "abs(-mountCircle / ( 2 * sqrt(2) ))")
  dimension "d835" diameter C4 = 4.3 (= "m4Clearance")
extrude "Extrude36" cut sketch "B Four Mount Holes" no distance stored
sketch "B M4 Nut Pocket 1" plane through (-0.3536, -0.3536, 0) normal (0.7071, 0.7071, 0) x axis (0, 0, 1)
  line L1 (24.7059, 26.2274) -> (26.7843, 22.6274)
  line L2 (20.549, 26.2274) -> (24.7059, 26.2274)
  line L3 (18.4705, 22.6274) -> (20.549, 26.2274)
  line L4 (20.549, 19.0274) -> (18.4705, 22.6274)
  line L5 (24.7059, 19.0274) -> (20.549, 19.0274)
  line L6 (26.7843, 22.6274) -> (24.7059, 19.0274)
  circle C1 centre (22.6274, 22.6274) radius 4.1569
  point P3 (26.7843, 22.6274)
  point P4 (24.7059, 26.2274)
  point P5 (20.549, 26.2274)
  point P6 (18.4705, 22.6274)
  point P7 (20.549, 19.0274)
  point P8 (24.7059, 19.0274)
  point P1 (0, 0)
  point P2 (22.6274, 22.6274)
  coincident C1 P3
  coincident C1 P4
  coincident C1 P5
  coincident C1 P6
  coincident C1 P7
  coincident C1 P8
  equal L1 L2
  equal L1 L3
  equal L1 L4
  equal L1 L5
  equal L1 L6
  horizontal L2
  dimension "d838" distance P1 P2 = 22.6274 (= "abs(mountCircle / ( 2 * sqrt(2) ))")
  dimension "d839" distance P1 P2 = 22.6274 (= "abs(mountCircle / ( 2 * sqrt(2) ))")
  dimension "d840" diameter C1 = 8.3138 (= "2 * ( nutAF ) / sqrt(3)")
extrude "Extrude37" cut sketch "B M4 Nut Pocket 1" profile of L1 L2 L3 L4 L5 L6 no distance stored
sketch "B M4 Nut Pocket 2" plane through (-0.3536, -0.3536, 0) normal (0.7071, 0.7071, 0) x axis (0, 0, 1)
  line L1 (-20.549, 26.2274) -> (-18.4705, 22.6274)
  line L2 (-24.7059, 26.2274) -> (-20.549, 26.2274)
  line L3 (-26.7843, 22.6274) -> (-24.7059, 26.2274)
  line L4 (-24.7059, 19.0274) -> (-26.7843, 22.6274)
  line L5 (-20.549, 19.0274) -> (-24.7059, 19.0274)
  line L6 (-18.4705, 22.6274) -> (-20.549, 19.0274)
  circle C1 centre (-22.6274, 22.6274) radius 4.1569
  point P3 (-18.4705, 22.6274)
  point P4 (-20.549, 26.2274)
  point P5 (-24.7059, 26.2274)
  point P6 (-26.7843, 22.6274)
  point P7 (-24.7059, 19.0274)
  point P8 (-20.549, 19.0274)
  point P1 (0, 0)
  point P2 (-22.6274, 22.6274)
  coincident C1 P3
  coincident C1 P4
  coincident C1 P5
  coincident C1 P6
  coincident C1 P7
  coincident C1 P8
  equal L1 L2
  equal L1 L3
  equal L1 L4
  equal L1 L5
  equal L1 L6
  horizontal L2
  dimension "d843" distance P1 P2 = 22.6274 (= "abs(-mountCircle / ( 2 * sqrt(2) ))")
  dimension "d844" distance P1 P2 = 22.6274 (= "abs(mountCircle / ( 2 * sqrt(2) ))")
  dimension "d845" diameter C1 = 8.3138 (= "2 * ( nutAF ) / sqrt(3)")
extrude "Extrude38" cut sketch "B M4 Nut Pocket 2" profile of L1 L2 L3 L4 L5 L6 no distance stored
sketch "B M4 Nut Pocket 3" plane through (-0.3536, -0.3536, 0) normal (0.7071, 0.7071, 0) x axis (0, 0, 1)
  line L1 (-20.549, -19.0274) -> (-18.4705, -22.6274)
  line L2 (-24.7059, -19.0274) -> (-20.549, -19.0274)
  line L3 (-26.7843, -22.6274) -> (-24.7059, -19.0274)
  line L4 (-24.7059, -26.2274) -> (-26.7843, -22.6274)
  line L5 (-20.549, -26.2274) -> (-24.7059, -26.2274)
  line L6 (-18.4705, -22.6274) -> (-20.549, -26.2274)
  circle C1 centre (-22.6274, -22.6274) radius 4.1569
  point P3 (-18.4705, -22.6274)
  point P4 (-20.549, -19.0274)
  point P5 (-24.7059, -19.0274)
  point P6 (-26.7843, -22.6274)
  point P7 (-24.7059, -26.2274)
  point P8 (-20.549, -26.2274)
  point P1 (0, 0)
  point P2 (-22.6274, -22.6274)
  coincident C1 P3
  coincident C1 P4
  coincident C1 P5
  coincident C1 P6
  coincident C1 P7
  coincident C1 P8
  equal L1 L2
  equal L1 L3
  equal L1 L4
  equal L1 L5
  equal L1 L6
  horizontal L2
  dimension "d848" distance P1 P2 = 22.6274 (= "abs(-mountCircle / ( 2 * sqrt(2) ))")
  dimension "d849" distance P1 P2 = 22.6274 (= "abs(-mountCircle / ( 2 * sqrt(2) ))")
  dimension "d850" diameter C1 = 8.3138 (= "2 * ( nutAF ) / sqrt(3)")
extrude "Extrude39" cut sketch "B M4 Nut Pocket 3" profile of L1 L2 L3 L4 L5 L6 no distance stored
sketch "B M4 Nut Pocket 4" plane through (-0.3536, -0.3536, 0) normal (0.7071, 0.7071, 0) x axis (0, 0, 1)
  line L1 (24.7059, -19.0274) -> (26.7843, -22.6274)
  line L2 (20.549, -19.0274) -> (24.7059, -19.0274)
  line L3 (18.4705, -22.6274) -> (20.549, -19.0274)
  line L4 (20.549, -26.2274) -> (18.4705, -22.6274)
  line L5 (24.7059, -26.2274) -> (20.549, -26.2274)
  line L6 (26.7843, -22.6274) -> (24.7059, -26.2274)
  circle C1 centre (22.6274, -22.6274) radius 4.1569
  point P3 (26.7843, -22.6274)
  point P4 (24.7059, -19.0274)
  point P5 (20.549, -19.0274)
  point P6 (18.4705, -22.6274)
  point P7 (20.549, -26.2274)
  point P8 (24.7059, -26.2274)
  point P1 (0, 0)
  point P2 (22.6274, -22.6274)
  coincident C1 P3
  coincident C1 P4
  coincident C1 P5
  coincident C1 P6
  coincident C1 P7
  coincident C1 P8
  equal L1 L2
  equal L1 L3
  equal L1 L4
  equal L1 L5
  equal L1 L6
  horizontal L2
  dimension "d853" distance P1 P2 = 22.6274 (= "abs(mountCircle / ( 2 * sqrt(2) ))")
  dimension "d854" distance P1 P2 = 22.6274 (= "abs(-mountCircle / ( 2 * sqrt(2) ))")
  dimension "d855" diameter C1 = 8.3138 (= "2 * ( nutAF ) / sqrt(3)")
extrude "Extrude40" cut sketch "B M4 Nut Pocket 4" profile of L1 L2 L3 L4 L5 L6 no distance stored
sketch "B Hub Service Slots" plane through (0, 0, 0) normal (0, 0, 1) x axis (1, 0, 0)
  line L1 (-30.4056, -12.0208) -> (-14.8492, 3.5355)
  line L2 (-12.0208, -30.4056) -> (-30.4056, -12.0208)
  line L3 (3.5355, -14.8492) -> (-12.0208, -30.4056)
  line L4 (-14.8492, 3.5355) -> (3.5355, -14.8492)
  point P1 (0, 0)
  point P2 (-14.8492, 3.5355)
  point P3 (-30.4056, -12.0208)
  point P4 (-12.0208, -30.4056)
  point P5 (3.5355, -14.8492)
  dimension "d858" distance P1 P2 = 14.8492 (= "abs(( -8 mm - 13 mm ) / sqrt(2))")
  dimension "d859" distance P1 P2 = 3.5355 (= "abs(( -8 mm + 13 mm ) / sqrt(2))")
  dimension "d860" distance P1 P3 = 30.4056 (= "abs(( -30 mm - 13 mm ) / sqrt(2))")
  dimension "d861" distance P1 P3 = 12.0208 (= "abs(( -30 mm + 13 mm ) / sqrt(2))")
  dimension "d862" distance P1 P4 = 12.0208 (= "abs(( -30 mm + 13 mm ) / sqrt(2))")
  dimension "d863" distance P1 P4 = 30.4056 (= "abs(( -30 mm - 13 mm ) / sqrt(2))")
  dimension "d864" distance P1 P5 = 3.5355 (= "abs(( -8 mm + 13 mm ) / sqrt(2))")
  dimension "d865" distance P1 P5 = 14.8492 (= "abs(( -8 mm - 13 mm ) / sqrt(2))")
extrude "Extrude41" cut sketch "B Hub Service Slots" distance 76 (= "mountOD")
chamfer "Chamfer2" distance 0.3 (= "bedRelief")
chamfer "Chamfer3" distance 0.5 (= "tubeCornerChamfer")
chamfer "Chamfer4" sketch "A Facet 135 Triangle 1" distance 0.3 (= "tubeRimChamfer")
work_plane "WorkPlane25" RotateAngle 0 ExtraOffset 0
work_plane "WorkPlane26" AlongDistance 75 (= "bodyWidth / 2") ExtraOffset 0
sketch "A End Cord Port" plane through (0, 0, 75) normal (0, 0, 1) x axis (1, 0, 0)
  line L1 (125, 0) -> (0, 0)
  circle C1 centre (125, 0) radius 2.25
  point P1 (0, 0)
  point P2 (125, 0)
  horizontal L1
  dimension "d875" distance P1 P2 = 125 (= "abs(( 1 ) * ( ( 1 ) * cordStation ) + ( 0 ) * ( 0 mm ))")
  dimension "d876" diameter C1 = 4.5
extrude "Extrude40" cut sketch "A End Cord Port" profile of C1 no distance stored
chamfer "Chamfer5" distance 0.3 (= "bedRelief")
work_plane "WorkPlane27" RotateAngle 180 ExtraOffset 0
work_plane "WorkPlane28" AlongDistance 75 (= "bodyWidth / 2") ExtraOffset 0
sketch "A End Cord Port (1)" plane through (0, 0, -75) normal (0, 0, -1) x axis (-1, 0, 0)
  line L1 (-125, 0) -> (0, 0)
  circle C1 centre (-125, 0) radius 2.25
  point P1 (0, 0)
  point P2 (-125, 0)
  horizontal L1
  dimension "d884" distance P1 P2 = 125 (= "abs(( -1 ) * ( ( 1 ) * cordStation ) + ( 0 ) * ( 0 mm ))")
  dimension "d885" diameter C1 = 4.5
extrude "Extrude41" cut sketch "A End Cord Port (1)" profile of C1 no distance stored
chamfer "Chamfer6" distance 0.3 (= "bedRelief")
chamfer "Chamfer1" distance 0.3 (= "bedRelief")
chamfer "Chamfer2" distance 0.5 (= "tubeCornerChamfer")
chamfer "Chamfer3" sketch "A Facet 135 Triangle 1" distance 0.3 (= "tubeRimChamfer")
work_plane "WorkPlane21" RotateAngle 0 ExtraOffset 0
work_plane "WorkPlane22" AlongDistance 75 (= "bodyWidth / 2") ExtraOffset 0
sketch "B End Cord Port" plane through (0, 0, 75) normal (0, 0, 1) x axis (1, 0, 0)
  line L1 (-125, 0) -> (0, 0)
  circle C1 centre (-125, 0) radius 2.25
  point P1 (0, 0)
  point P2 (-125, 0)
  horizontal L1
  dimension "d896" distance P1 P2 = 125 (= "abs(( 1 ) * ( ( -1 ) * cordStation ) + ( 0 ) * ( 0 mm ))")
  dimension "d897" diameter C1 = 4.5
extrude "Extrude42" cut sketch "B End Cord Port" profile of C1 no distance stored
chamfer "Chamfer4" distance 0.3 (= "bedRelief")
work_plane "WorkPlane23" RotateAngle 180 ExtraOffset 0
work_plane "WorkPlane24" AlongDistance 75 (= "bodyWidth / 2") ExtraOffset 0
sketch "B End Cord Port (1)" plane through (0, 0, -75) normal (0, 0, -1) x axis (-1, 0, 0)
  line L1 (125, 0) -> (0, 0)
  circle C1 centre (125, 0) radius 2.25
  point P1 (0, 0)
  point P2 (125, 0)
  horizontal L1
  dimension "d905" distance P1 P2 = 125 (= "abs(( -1 ) * ( ( -1 ) * cordStation ) + ( 0 ) * ( 0 mm ))")
  dimension "d906" diameter C1 = 4.5
extrude "Extrude43" cut sketch "B End Cord Port (1)" profile of C1 no distance stored
chamfer "Chamfer5" distance 0.3 (= "bedRelief")
work_plane "WorkPlane1" AlongDistance 22.6 (= "qRearBase") ExtraOffset 0
sketch "D Rear Holder Blank sketch" plane through (15.9806, 15.9806, 0) normal (0.7071, 0.7071, 0) x axis (0, 0, 1)
  circle C1 centre (0, 0) radius 22
  dimension "d912" diameter C1 = 44 (= "coreOD")
extrude "Extrude1" new body sketch "D Rear Holder Blank sketch" along normal blind 10.2 (= "shoulder + rearSeatDepth")
work_plane "WorkPlane2" AlongDistance 22.6 (= "qRearBase") ExtraOffset 0
sketch "D Seal Relief sketch" plane through (15.9806, 15.9806, 0) normal (0.7071, 0.7071, 0) x axis (0, 0, 1)
  circle C1 centre (0, 0) radius 9.75
  dimension "d917" diameter C1 = 19.5 (= "raceRelief")
extrude "Extrude2" cut sketch "D Seal Relief sketch" along normal blind 10.2 (= "shoulder + rearSeatDepth")
work_plane "WorkPlane3" AlongDistance 25.6 (= "qRearBearing") ExtraOffset 0
sketch "D Rear Bearing Seat sketch" plane through (18.1019, 18.1019, 0) normal (0.7071, 0.7071, 0) x axis (0, 0, 1)
  circle C1 centre (0, 0) radius 11.1
  dimension "d922" diameter C1 = 22.2 (= "seatDiameter")
extrude "Extrude3" cut sketch "D Rear Bearing Seat sketch" along normal blind 7.2 (= "rearSeatDepth")
work_plane "WorkPlane4" AlongDistance 22.6 (= "qRearBase") ExtraOffset 0
sketch "D Support Bolt seed" plane through (15.9806, 15.9806, 0) normal (0.7071, 0.7071, 0) x axis (0, 0, 1)
  line L1 (17, 0) -> (0, 0)
  circle C1 centre (17, 0) radius 1.65
  point P1 (0, 0)
  point P2 (17, 0)
  horizontal L1
  dimension "d927" distance P1 P2 = 17 (= "supportCircle / 2")
  dimension "d928" diameter C1 = 3.3 (= "m3Clearance")
extrude "Extrude4" cut sketch "D Support Bolt seed" profile of C1 along normal blind 10.2 (= "shoulder + rearSeatDepth")
circular_pattern "C-Pattern1" TotalAngle 360
chamfer "Chamfer1" distance 0.4 (= "entryChamfer")
chamfer "Chamfer2" distance 0.3 (= "bedRelief")
work_plane "WorkPlane1" AlongDistance -2.5 (= "qFront - capThickness") ExtraOffset 0
sketch "C Front Bearing Cap Ring sketch" plane through (-1.7678, -1.7678, 0) normal (0.7071, 0.7071, 0) x axis (0, 0, 1)
  circle C1 centre (0, 0) radius 22
  circle C2 centre (0, 0) radius 9.75
  dimension "d937" diameter C1 = 44 (= "coreOD")
  dimension "d938" diameter C2 = 19.5 (= "raceRelief")
extrude "Extrude1" new body sketch "C Front Bearing Cap Ring sketch" along normal blind 3 (= "capThickness")
work_plane "WorkPlane2" AlongDistance -2.5 (= "qFront - capThickness") ExtraOffset 0
sketch "C Front Bearing Cap Bolt seed" plane through (-1.7678, -1.7678, 0) normal (0.7071, 0.7071, 0) x axis (0, 0, 1)
  line L1 (17, 0) -> (0, 0)
  circle C1 centre (17, 0) radius 1.65
  point P1 (0, 0)
  point P2 (17, 0)
  horizontal L1
  dimension "d943" distance P1 P2 = 17 (= "supportCircle / 2")
  dimension "d944" diameter C1 = 3.3 (= "m3Clearance")
extrude "Extrude2" cut sketch "C Front Bearing Cap Bolt seed" profile of C1 along normal blind 3 (= "capThickness")
circular_pattern "C-Pattern1" TotalAngle 360
chamfer "Chamfer1" distance 0.3 (= "bedRelief")
work_plane "WorkPlane1" AlongDistance 32.8 (= "qRearEnd") ExtraOffset 0
sketch "E Rear Bearing Cap Ring sketch" plane through (23.1931, 23.1931, 0) normal (0.7071, 0.7071, 0) x axis (0, 0, 1)
  circle C1 centre (0, 0) radius 22
  circle C2 centre (0, 0) radius 9.75
  dimension "d952" diameter C1 = 44 (= "coreOD")
  dimension "d953" diameter C2 = 19.5 (= "raceRelief")
extrude "Extrude1" new body sketch "E Rear Bearing Cap Ring sketch" along normal blind 3 (= "capThickness")
work_plane "WorkPlane2" AlongDistance 32.8 (= "qRearEnd") ExtraOffset 0
sketch "E Rear Bearing Cap Bolt seed" plane through (23.1931, 23.1931, 0) normal (0.7071, 0.7071, 0) x axis (0, 0, 1)
  line L1 (17, 0) -> (0, 0)
  circle C1 centre (17, 0) radius 1.65
  point P1 (0, 0)
  point P2 (17, 0)
  horizontal L1
  dimension "d958" distance P1 P2 = 17 (= "supportCircle / 2")
  dimension "d959" diameter C1 = 3.3 (= "m3Clearance")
